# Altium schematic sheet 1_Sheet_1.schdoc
size 215 x 154 mm; Name: A_Customize; Symbol: A_Customize; Device: A_Customize; @Project Name: MUSIC RYTHM_2026-10-30_13-18-21; REV: 1.0; Date: 2026-02-13; Sheet: 1/1; Draw By: Shubh malhotra; Company: Your Company; Convert to PCB: yes; Add into BOM: yes; spicePre: .; @Page No: 1; @Page Count: 1; @Schematic Name: MUSIC RYTHM; @Board Name: MUSIC RYTHM; @Update Date: 2026-10-30; @Create Time: 07:48:24; @Update Time: 13:18:29; @Page Name: Sheet_1; @Create Date: 2026-10-30
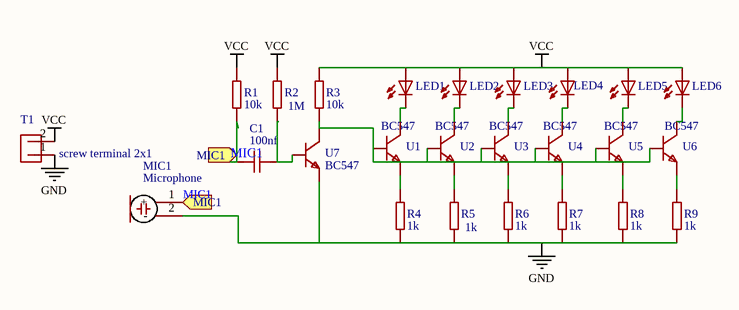
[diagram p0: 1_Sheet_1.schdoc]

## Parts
C1  100nf
LED1  LED_5MM COPY COPY  [LED-5MM-5MM]  (value not drawn)
LED2  LED_5MM COPY COPY  [LED-5MM-5MM]  (value not drawn)
LED3  LED_5MM COPY COPY  [LED-5MM-5MM]  (value not drawn)
LED4  LED_5MM COPY COPY  [LED-5MM-5MM]  (value not drawn)
LED5  LED_5MM COPY COPY  [LED-5MM-5MM]  (value not drawn)
LED6  LED_5MM COPY COPY  [LED-5MM-5MM]  (value not drawn)
MIC1  Microphone  [MICROPHONE]
R1  10k  [RTH025W]
R2  1M  [RTH025W]
R3  10k  [RTH025W]
R4  1k  [RTH025W]
R5  1k  [RTH025W]
R6  1k  [RTH025W]
R7  1k  [RTH025W]
R8  1k  [RTH025W]
R9  1k  [RTH025W]
T1  screw terminal 2x1  [M02 SCREW TERMINAL 5MM 10X8MM]
U1  BC547  [TRANS NPN]
U2  BC547  [TRANS NPN]
U3  BC547  [TRANS NPN]
U4  BC547  [TRANS NPN]
U5  BC547  [TRANS NPN]
U6  BC547  [TRANS NPN]
U7  BC547  [TRANS NPN]

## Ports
MIC1 (in)

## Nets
GND: MIC1.2(-) R4.1 R5.1 R6.1 R7.1 R8.1 R9.1 T1.1 U7.3(E)
VCC: LED1.1(A) LED2.1(A) LED3.1(A) LED4.1(A) LED5.1(A) LED6.1(A) R1.2 R2.2 R3.2 T1.2
MIC1: C1.1 MIC1.1(+) R1.1 ; port MIC1
NetC1_2: C1.2 R2.1 U7.2(B)
NetLED1_2: LED1.2(C) U1.1(C)
NetLED2_2: LED2.2(C) U2.1(C)
NetLED3_2: LED3.2(C) U3.1(C)
NetLED4_2: LED4.2(C) U4.1(C)
NetLED5_2: LED5.2(C) U5.1(C)
NetLED6_2: LED6.2(C) U6.1(C)
NetR3_1: R3.1 U1.2(B) U2.2(B) U3.2(B) U4.2(B) U5.2(B) U6.2(B) U7.1(C)
NetR4_2: R4.2 U1.3(E)
NetR5_2: R5.2 U2.3(E)
NetR6_2: R6.2 U3.3(E)
NetR7_2: R7.2 U4.3(E)
NetR8_2: R8.2 U5.3(E)
NetR9_2: R9.2 U6.3(E)

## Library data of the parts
C1 = 100nf: Manufacturer: Dersonic(德尔创); Manufacturer Part: CC1H102MA1EDB44B1100; Convert to PCB: yes; Origin Footprint: CAP-TH_L4.8-W2.8-P2.54-D0.7; nameAlias: Value; Contributor: lcsc
LED1 = LED_5MM COPY COPY: Manufacturer Part: 333-2SURD/S530-A3; Manufacturer: EVERLIGHT(亿光); Convert to PCB: yes; Contributor: Airtau; Package Display: No
LED2-LED6 = LED_5MM COPY COPY: Manufacturer Part: 333-2SURD/S530-A3; Manufacturer: EVERLIGHT(亿光); Convert to PCB: yes; Contributor: Airtau
MIC1 = Microphone: Manufacturer: CUI Devices; Manufacturer Part: CMC-97452-L100; Convert to PCB: yes; Contributor: PiotrSt
R1 R3 = 10k: Manufacturer Part: CR1/4W-10K±5%-ST26; Manufacturer: VO(翔胜); Convert to PCB: yes; Contributor: DangerousPrototype
R2 = 1M: Manufacturer Part: CR1/4W-1M±5%-ST52; Manufacturer: VO(翔胜); Convert to PCB: yes; Contributor: DangerousPrototype
R4-R9 = 1k: Manufacturer Part: CR1/4W-1K±5%-RT52; Manufacturer: VO(翔胜); Convert to PCB: yes; Contributor: DangerousPrototype
T1 = screw terminal 2x1: Manufacturer: JILN(锦凌); Manufacturer Part: JL128-50802G01; Convert to PCB: yes; Contributor: serioga.com
U1-U7 = BC547: Manufacturer: onsemi(安森美); Manufacturer Part: BC547CTA; Convert to PCB: yes; Contributor: angelkastro234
